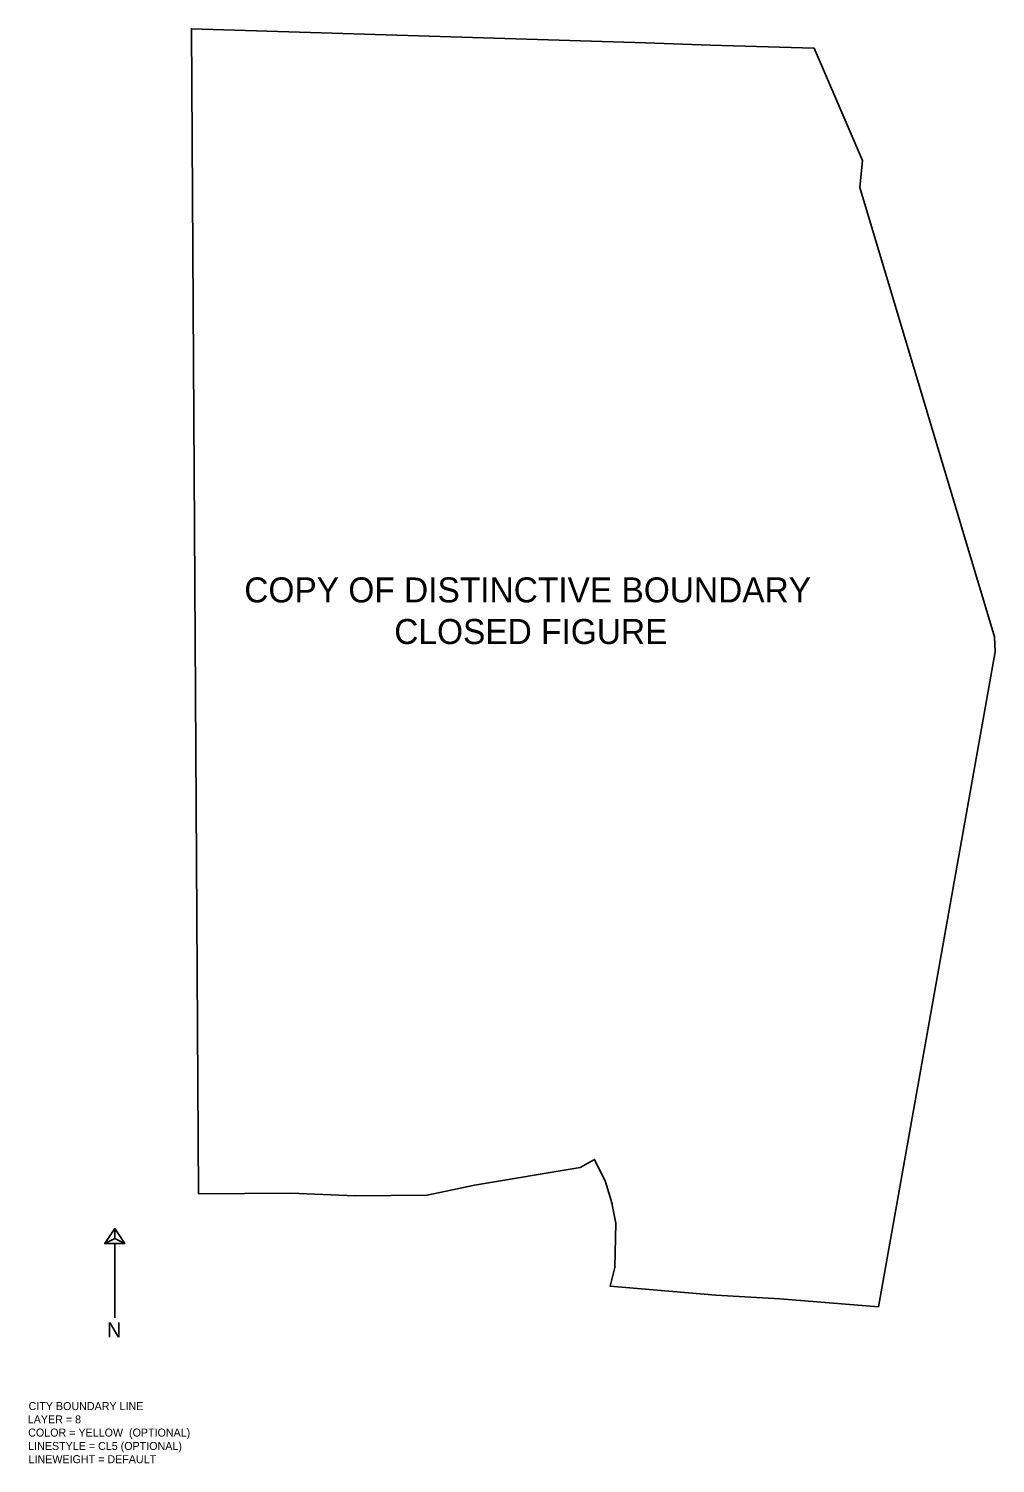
# Model space of a CAD drawing. Extents: x 6387474 to 6390971, y 1972046 to 1973920.
# Drawn here: x 6390005 to 6390971, y 1972119 to 1973553 of the extents above; entities that cross this region are included whole.
import ezdxf

# ---------------------------------------------------------------- set-up
doc = ezdxf.new("R2010")
doc.units = 0
doc.layers.add('8', color=7, linetype='Continuous')
doc.layers.add('REFERENCE GUIDE TEXT', color=7, linetype='Continuous')

msp = doc.modelspace()

# ---------------------------------------------------------------- linework, layer by layer
at = {"layer": '8'}
for p, q in [((6390090.6, 1972353.2), (6390080.6, 1972338.2)), ((6390090.6, 1972353.2), (6390100.6, 1972338.2)), ((6390080.6, 1972338.2), (6390100.6, 1972338.2)), ((6390090.6, 1972264), (6390090.6, 1972338.2))]:
    msp.add_line(p, q, dxfattribs=at)
msp.add_lwpolyline([(6390838, 1973420.9), (6390835.2, 1973394.1), (6390969.8, 1972944.7), (6390970.7, 1972929.7), (6390853.8, 1972275), (6390755.4, 1972283), (6390691.5, 1972286.8), (6390585.7, 1972295.8), (6390590.5, 1972314.4), (6390591.4, 1972358.8), (6390587.8, 1972377.1), (6390587.6, 1972378.1), (6390581.1, 1972399.8), (6390570.1, 1972422.3), (6390555.8, 1972414.4), (6390450.2, 1972396.7), (6390402.7, 1972386.5), (6390330.7, 1972386), (6390266.7, 1972388.6), (6390174.2, 1972388), (6390167.1, 1973552.7), (6390621.2, 1973538.5), (6390685.9, 1973536.4), (6390789.5, 1973533.2), (6390838, 1973420.9)], dxfattribs=at)
for points in [[(6390090.6, 1972343.2), (6390080.6, 1972338.2), (6390090.6, 1972353.2)], [(6390090.6, 1972343.2), (6390090.6, 1972353.2), (6390100.6, 1972338.2)], [(6390090.6, 1972343.2), (6390100.6, 1972338.2), (6390080.6, 1972338.2)]]:
    msp.add_lwpolyline(points, close=True, dxfattribs=at)

# ---------------------------------------------------------------- texts
for s, height, p in [('N', 15, (6390082.7, 1972244.5)), ('CITY BOUNDARY LINE', 8, (6390004.4, 1972171.8)), ('LAYER = 8', 8, (6390003.6, 1972158.5)), ('COLOR = YELLOW  (OPTIONAL)', 8, (6390004, 1972145.3)), ('LINESTYLE = CL5 (OPTIONAL)', 8, (6390004, 1972131.9)), ('LINEWEIGHT = DEFAULT', 8, (6390004.4, 1972118.7))]:
    msp.add_text(s, height=height, dxfattribs=at).set_placement(p)
at = {"layer": 'REFERENCE GUIDE TEXT'}
for s, p in [('COPY OF DISTINCTIVE BOUNDARY', (6390220, 1972979.2)), ('                CLOSED FIGURE', (6390221.3, 1972937.6))]:
    msp.add_text(s, height=25, dxfattribs=at).set_placement(p)

doc.saveas('drawing.dxf')
